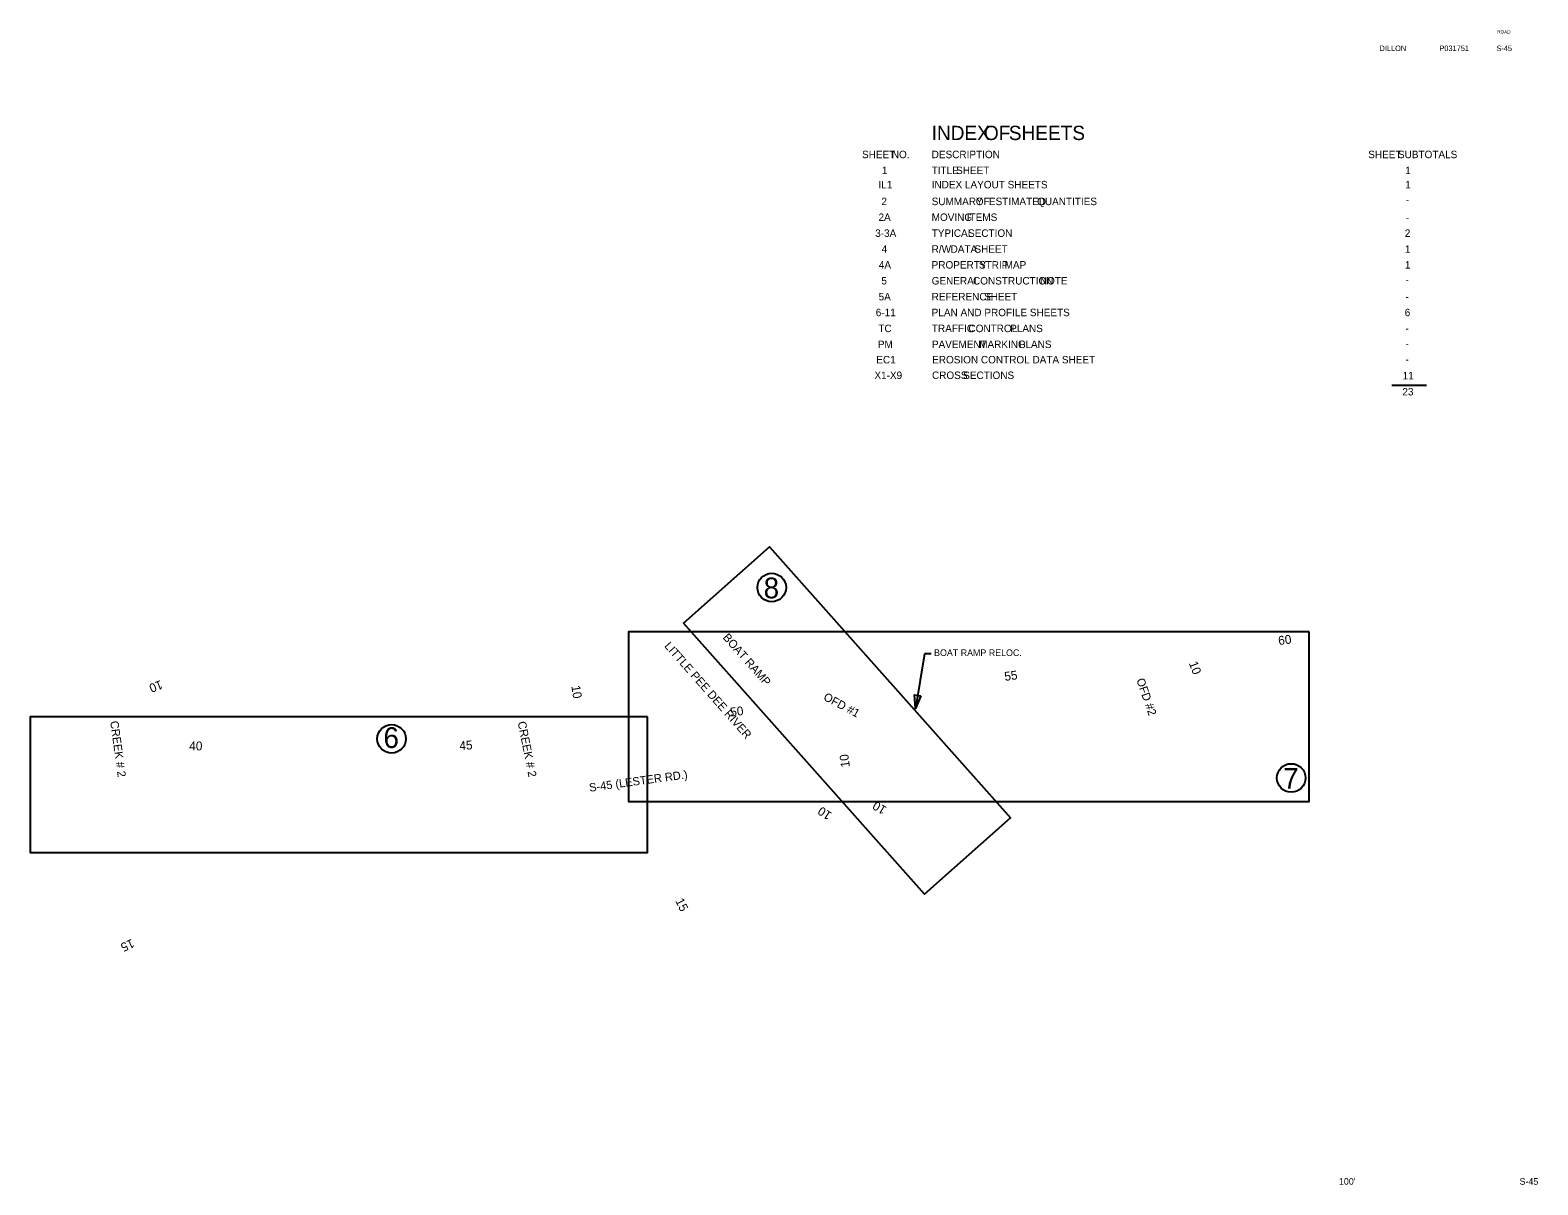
# Model space of a CAD drawing. Extents: x 170379 to 171743, y 223178 to 224223.
import ezdxf

# ---------------------------------------------------------------- set-up
doc = ezdxf.new("R2010")
doc.units = 0
for name, color, linetype in [('Default', 7, 'Continuous'), ('RD_HC_Data_Rel', 7, 'Continuous'), ('RD_HC_TX_Rel_Sta50', 7, 'Continuous'), ('RD_HC_TX_Sta50', 7, 'Continuous'), ('RD_SHT_TX', 7, 'Continuous'), ('RD_TX_Drainage', 7, 'Continuous'), ('RD_TX_RoadID', 7, 'Continuous')]:
    doc.layers.add(name, color=color, linetype=linetype)

msp = doc.modelspace()

# ---------------------------------------------------------------- linework, layer by layer
at = {"layer": 'Default'}
for points in [[(170969.7, 223686), (171047.5, 223755.1), (171265.5, 223510), (171187.7, 223440.9)], [(171536, 223678.2), (170920.1, 223678.2), (170920.1, 223524.6), (171536, 223524.6)], [(170937.3, 223601.2), (170378.6, 223601.2), (170378.6, 223478.5), (170937.3, 223478.5)]]:
    msp.add_lwpolyline(points, close=True, dxfattribs=at)
for centre in [(171049.6, 223718.3), (170705.6, 223581.4), (171519.6, 223546)]:
    msp.add_circle(centre, 12.9, dxfattribs=at)
at = {"layer": 'RD_HC_Data_Rel'}
for p, q in [((171187.9, 223658.4), (171179.7, 223608.9)), ((171193.9, 223658.4), (171187.9, 223658.4))]:
    msp.add_line(p, q, dxfattribs=at)
at = {"layer": 'RD_TX_Drainage'}
msp.add_line((171610.6, 223901.3), (171642.1, 223901.3), dxfattribs=at)
msp.add_lwpolyline([(171184.6, 223620.3), (171179.7, 223608.9), (171178.7, 223621.2)], close=True, dxfattribs=at)

# ---------------------------------------------------------------- texts
at = {"layer": 'Default'}
for s, p in [('8', (171042.3, 223708.5)), ('6', (170698.3, 223573.1)), ('7', (171512.3, 223536.2))]:
    msp.add_text(s, height=18.8, dxfattribs=at).set_placement(p)
at = {"layer": 'RD_HC_Data_Rel'}
msp.add_text('BOAT RAMP RELOC.', height=6, dxfattribs=at).set_placement((171196.5, 223656.3))
at = {"layer": 'RD_HC_TX_Rel_Sta50'}
msp.add_text('10', height=8, rotation=97.4359, dxfattribs=at).set_placement((171120.3, 223556.1))
at = {"layer": 'RD_HC_TX_Sta50'}
for s, rotation, p in [('60', 7.4359, (171508.4, 223666.2)), ('55', 7.4359, (171260.6, 223633.8)), ('10', 290.5732, (171426.9, 223649.9)), ('10', 201.1731, (170496.6, 223634.7)), ('10', 279.3211, (170868.2, 223629.1)), ('50', 7.4359, (171012.6, 223601.5)), ('40', 359.0421, (170522.5, 223571.1)), ('45', 4.5104, (170767.3, 223571.1)), ('10', 146.5147, (171104.6, 223514)), ('10', 148.8891, (171154.2, 223519.2)), ('15', 296.2952, (170962.1, 223434.9)), ('15', 204.5829, (170470.5, 223400.6))]:
    msp.add_text(s, height=8, rotation=rotation, dxfattribs=at).set_placement(p)
at = {"layer": 'RD_SHT_TX'}
for s, height, p in [('ROAD', 3, (171706.1, 224219.6)), ('DILLON', 5, (171599.5, 224203.7)), ('P031751', 5, (171653.7, 224203.7)), ('S-45', 5, (171705.3, 224203.7)), ("100'", 6, (171562.8, 223177.9)), ('S-45', 6, (171726.2, 223177.9))]:
    msp.add_text(s, height=height, dxfattribs=at).set_placement(p)
at = {"layer": 'RD_TX_Drainage'}
for s, height, p in [('INDEX', 12.89, (171194.3, 224123.2)), ('INDEX', 12.89, (171194.3, 224123.2)), ('INDEX', 12.89, (171194.3, 224123.2)), (' OF', 12.89, (171236.8, 224123.2)), (' OF', 12.89, (171236.8, 224123.2)), (' OF', 12.89, (171236.8, 224123.2)), (' SHEETS', 12.89, (171259.3, 224123.2)), (' SHEETS', 12.89, (171259.3, 224123.2)), (' SHEETS', 12.89, (171259.3, 224123.2)), ('SHEET', 6.75, (171131.3, 224106.8)), (' NO.', 6.75, (171155.7, 224106.8)), ('DESCRIPTION', 6.754, (171194.3, 224106.8)), ('SHEET', 6.75, (171589.3, 224106.8)), (' SUBTOTALS', 6.75, (171613.7, 224106.8)), ('1', 6.75, (171149.3, 224092.4)), ('TITLE', 6.75, (171194.3, 224092.4)), (' SHEET', 6.75, (171213.9, 224092.4)), ('1', 6.75, (171622.8, 224092.4)), ('IL1', 6.75, (171146.2, 224079.5)), ('INDEX LAYOUT SHEETS', 6.754, (171194.3, 224079.5)), ('1', 6.75, (171622.8, 224079.5)), ('2', 6.75, (171148.8, 224064.3)), ('SUMMARY', 6.75, (171194.3, 224064.3)), (' OF', 6.75, (171231.7, 224064.3)), (' ESTIMATED', 6.75, (171243.6, 224064.3)), (' QUANTITIES', 6.754, (171287.2, 224064.3)), ('-', 6.75, (171623.3, 224065.8)), ('2A', 6.75, (171146.2, 224050)), ('MOVING', 6.75, (171194.3, 224050)), (' ITEMS', 6.75, (171223.6, 224050)), ('-', 6.75, (171623.3, 224049.7)), ('3-3A', 6.75, (171143.2, 224035.6)), ('TYPICAL', 6.75, (171194.3, 224035.6)), (' SECTION', 6.75, (171224.7, 224035.6)), ('2', 6.75, (171622.4, 224035.6)), ('4', 6.75, (171149, 224021.2)), ('R/W', 6.75, (171194.3, 224021.2)), (' DATA', 6.75, (171208.9, 224021.2)), (' SHEET', 6.75, (171230.5, 224021.2)), ('1', 6.75, (171622.5, 224021.2)), ('4A', 6.75, (171146.5, 224006.9)), ('PROPERTY', 6.75, (171194.3, 224006.9)), (' STRIP', 6.75, (171234.6, 224006.9)), (' MAP', 6.75, (171257.8, 224006.9)), ('1', 6.75, (171622.5, 224006.9)), ('5', 6.75, (171148.8, 223992.5)), ('GENERAL', 6.75, (171194.3, 223992.5)), (' CONSTRUCTION', 6.754, (171229.2, 223992.5)), (' NOTE', 6.75, (171289.7, 223992.5)), ('-', 6.75, (171623, 223993.3)), ('5A', 6.75, (171146.3, 223978.1)), ('REFERENCE', 6.75, (171194.3, 223978.1)), (' SHEET', 6.75, (171239.2, 223978.1)), ('-', 6.75, (171623.1, 223978.1)), ('6-11', 6.75, (171143.7, 223963.8)), ('PLAN AND PROFILE SHEETS', 6.754, (171194.3, 223963.8)), ('6', 6.75, (171622.3, 223963.8)), ('TC', 6.75, (171146.1, 223949.4)), ('TRAFFIC', 6.75, (171194.5, 223949.4)), (' CONTROL', 6.75, (171225.1, 223949.4)), (' PLANS', 6.75, (171262.8, 223949.4)), ('PM', 6.75, (171145.6, 223935)), ('PAVEMENT', 6.75, (171194.5, 223935)), (' MARKING', 6.75, (171234.8, 223935)), (' PLANS', 6.75, (171270.6, 223935)), ('-', 6.75, (171623, 223949.4)), ('EC1', 6.75, (171144.2, 223921.1)), ('EROSION CONTROL DATA SHEET', 6.754, (171194.7, 223921.1)), ('-', 6.75, (171623, 223935.5)), ('X1-X9', 6.75, (171142.5, 223907)), ('CROSS', 6.75, (171194.6, 223907)), (' SECTIONS', 6.75, (171220.3, 223907)), ('11', 6.75, (171620.4, 223906.7)), ('-', 6.75, (171623, 223921.4)), ('23', 6.75, (171620.2, 223892.1))]:
    msp.add_text(s, height=height, dxfattribs=at).set_placement(p)
at = {"layer": 'RD_TX_RoadID'}
for s, rotation, p in [('LITTLE PEE DEE RIVER', 311.3831, (170952, 223665.1)), ('BOAT RAMP', 311.3831, (171004.8, 223672.8)), ('OFD #2', 289.0823, (171379.4, 223634.8)), ('OFD #1', 331.8245, (171095.7, 223617)), ('CREEK # 2', 277.8022, (170451, 223597.1)), ('CREEK # 2', 281.1706, (170819.7, 223596.5)), ('S-45 (LESTER RD.)', 7.8022, (170884.9, 223533.5))]:
    msp.add_text(s, height=7.5, rotation=rotation, dxfattribs=at).set_placement(p)

doc.saveas('drawing.dxf')
